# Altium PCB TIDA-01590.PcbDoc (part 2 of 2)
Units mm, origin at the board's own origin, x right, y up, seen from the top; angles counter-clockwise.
Board outline 129.16 x 83.44 mm, 2 copper layers (Top Layer, Bottom Layer), stack 1.646 mm thick; 71 components, 28 nets, 172 pads, 183 vias.
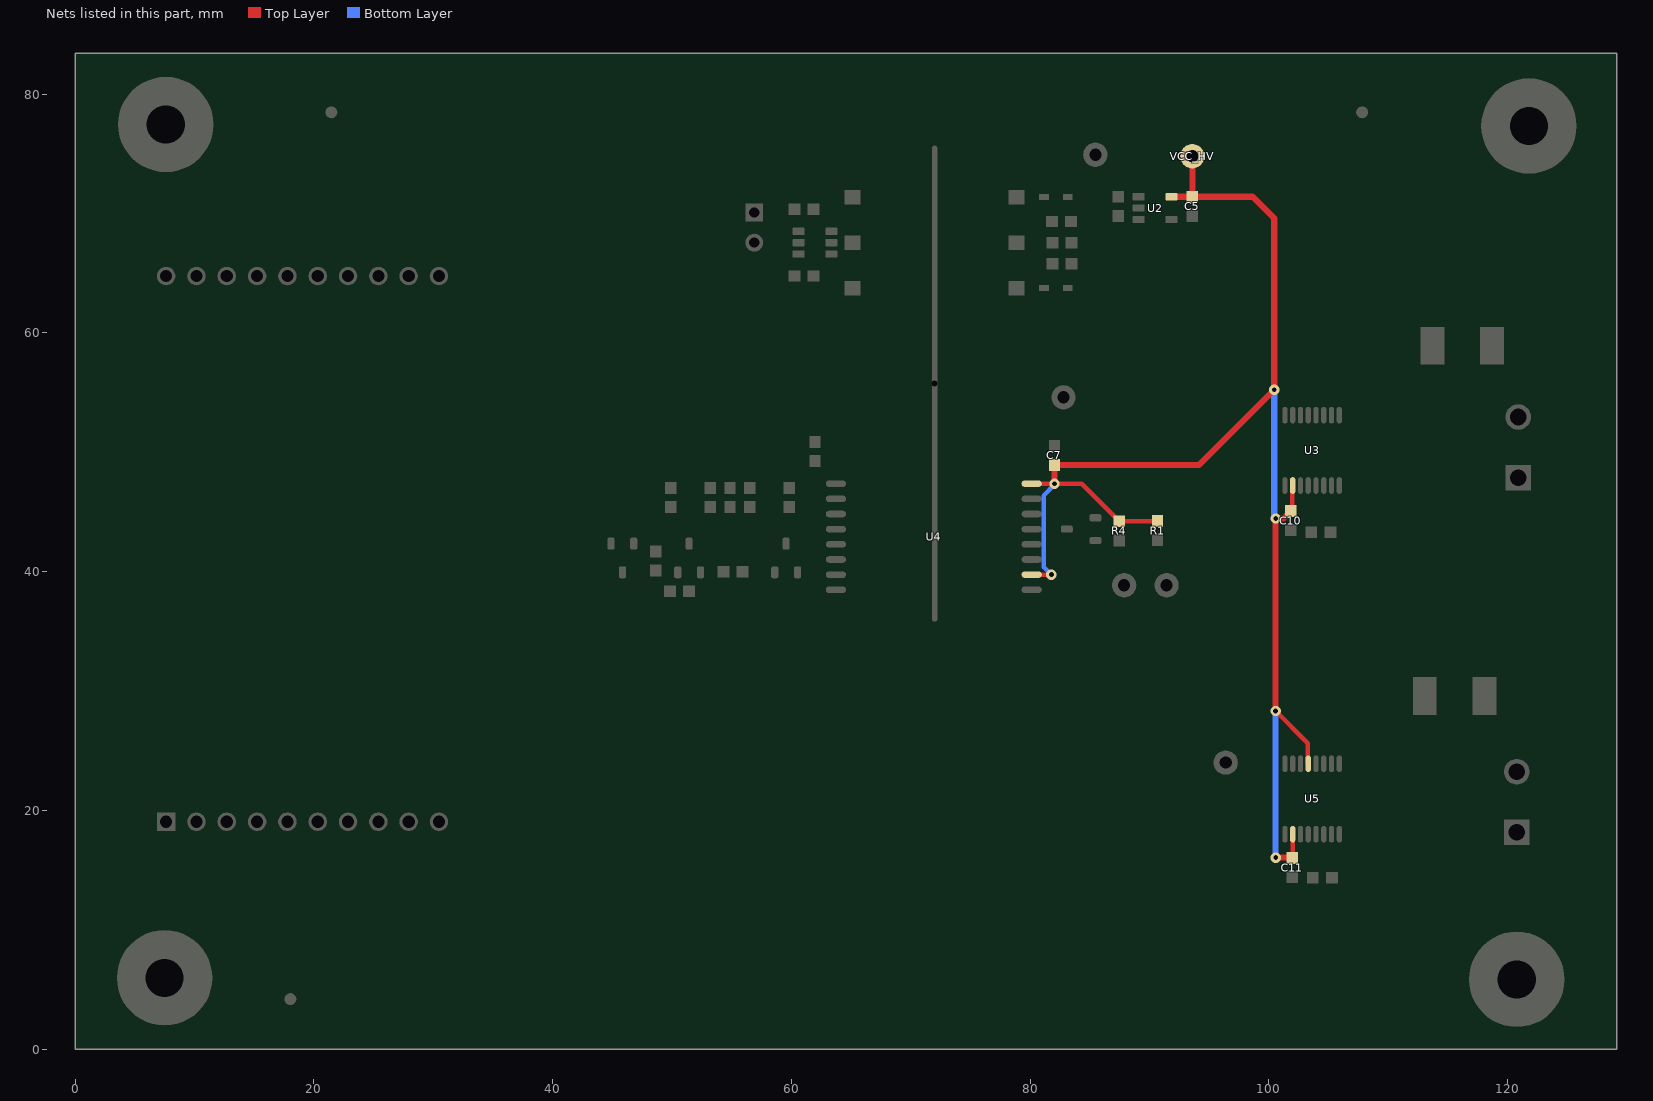
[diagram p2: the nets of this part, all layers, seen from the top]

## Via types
v1: diameter 0.864, hole 0.406, Top Layer to Bottom Layer, tented both sides, 182 vias
v2: diameter 0.965, hole 0.508, Top Layer to Bottom Layer, tented both sides, 1 vias

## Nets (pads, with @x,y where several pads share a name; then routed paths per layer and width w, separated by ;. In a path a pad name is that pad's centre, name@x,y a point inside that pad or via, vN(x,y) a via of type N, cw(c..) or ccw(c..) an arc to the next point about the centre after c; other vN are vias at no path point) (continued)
VCC_HV: C5.1 C7.2 C10.1 C11.1 R1.2 R4.2 U2.5 U3.10 U4.10 U4.16 U5.5 U5.10 VCC_HV.1 | length 123.1
  Top Layer w0.254: 84.328,47.355 84.328,47.371 ; R1.2@90.667,44.223 R1.2@90.678,44.234
  Top Layer w0.381: U4.10@80.209,39.751 v1(81.788,39.751) ; U4.16@80.391,47.371 v1(82.042,47.371) 84.328,47.371 ; 84.328,47.355 R4.2@87.46,44.223 R1.2@90.667,44.223 ; v1(100.575,28.321) 103.276,25.62 103.276,23.936 U5.5@103.307,23.905 ; C10.1@101.854,45.085 101.976,45.207 101.976,47.184 U3.10@102.007,47.215 ; C11.1@101.939,16.044 102.007,16.112 U5.10@102.007,18.005 U5.10@101.981,17.979
  Top Layer w0.508: v1(82.042,47.371) C7.2@82.042,48.946 94.158,48.946 v1(100.457,55.245) 100.457,69.596 98.641,71.412 C5.1@93.599,71.412 ; U2.5@91.853,71.409 93.596,71.409 C5.1@93.599,71.412 ; VCC_HV.1@93.599,74.803 C5.1@93.599,71.412 ; v1(100.575,28.321) 100.575,44.441 v1(100.584,44.45) 101.219,44.45 C10.1@101.854,45.085 ; v1(100.584,16.044) C11.1@101.939,16.044
  Bottom Layer w0.381: v1(81.788,39.751) 81.153,40.386 81.153,46.379 82.042,47.268 v1(82.042,47.371)
  Bottom Layer w0.508: v1(100.457,55.245) 100.457,44.577 v1(100.584,44.45) ; v1(100.575,28.321) 100.575,16.053 v1(100.584,16.044)
pads on no net: D3.2 D4.2 D5.2 FID1.1 FID2.1 FID3.1 H1.1 H2.1 H3.1 H4.1 H8.0 J4.2 J4.3 J4.4 J4.6 J4.7 J4.8 J5.11 J5.12 J5.13 J5.14 J5.15 J5.16 J5.17 J5.18 J5.19 U2.3 U2.4 U3.12 U3.13 U5.12 U5.13

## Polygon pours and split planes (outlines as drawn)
NetJ3_1 on Top Layer "TOP_LAYER_NETJ3_1_P154" (solid, remove dead copper, pour order 154): 104.394,20.667 104.394,16.222 104.394,15.658 104.394,9.525 105.156,8.763 105.881,8.038 120.04,8.038 124.841,14.039 124.841,20.667
NetF1_2 on Top Layer "TOP_LAYER_NETF1_2_P149" (solid, remove dead copper, pour order 149): 104.267,50.165 115.951,50.165 115.951,66.294 105.664,66.294 104.267,64.897
NetF1_1 on Top Layer "TOP_LAYER_NETF1_1_P147" (solid, remove dead copper, pour order 147): 115.951,50.292 124.841,50.292 124.841,65.165 123.917,66.294 115.951,66.294
NetJ2_1 on Top Layer "TOP_LAYER_NETJ2_1_P135" (solid, remove dead copper, pour order 135): 104.394,50.094 104.394,45.649 104.394,45.085 104.394,38.862 105.791,37.465 120.04,37.465 124.841,43.466 124.841,50.094
GND_HV on Top Layer "TOP_LAYER_GND_HV_P140" (solid, remove dead copper, pour order 140): 78.232,73.66 78.232,65.405 79.629,63.881 81.534,61.976 98.425,61.976 99.441,62.865 100.076,63.5 100.076,73.787 98.044,75.819 81.471,75.819
GND on Top Layer "TOP_LAYER_GND_P139" (solid, remove dead copper, pour order 139): 38.735,33.755 38.735,50.165 43.18,54.61 62.23,54.61 63.119,53.721 64.262,52.578 64.262,33.685 60.745,30.988 42.259,30.988
GND_HV on Top Layer "TOP_LAYER_GND_HV_P132" (solid, remove dead copper, pour order 132): 101.981,59.055 82.169,59.055 79.629,56.515 79.629,17.246 88.71,8.001 102.616,8.001 104.14,9.525 104.14,56.896
GND on Top Layer "TOP_LAYER_GND_P138" (solid, remove dead copper, pour order 138): 38.735,74.168 38.735,62.103 43.18,57.658 61.468,57.658 62.865,59.055 64.262,60.452 64.262,73.533 64.008,73.787 61.976,75.819 40.386,75.819
NetF2_1 on Top Layer "TOP_LAYER_NETF2_1_P131" (solid, remove dead copper, pour order 131): 115.951,20.701 124.841,20.701 124.841,35.701 123.917,36.83 115.951,36.83
NetF2_2 on Top Layer "TOP_LAYER_NETF2_2_P148" (solid, remove dead copper, pour order 148): 104.14,20.701 115.951,20.701 115.951,36.83 105.791,36.83 104.14,35.179
NetJ3_1 on Bottom Layer "BOTTOM_LAYER_NETJ3_1_P153" (solid, remove dead copper, pour order 153): 104.394,20.574 104.394,16.222 104.394,15.658 104.394,9.525 105.881,8.038 120.04,8.038 124.841,14.039 124.841,20.574
NetF1_1 on Bottom Layer "BOTTOM_LAYER_NETF1_1_P150" (solid, remove dead copper, pour order 150): 115.951,50.292 124.841,50.292 124.841,65.165 123.917,66.294 115.951,66.294
NetF1_2 on Bottom Layer "BOTTOM_LAYER_NETF1_2_P151" (solid, remove dead copper, pour order 151): 104.267,50.165 115.951,50.165 115.951,66.294 105.664,66.294 104.267,64.897
GND_HV on Bottom Layer "BOTTOM_LAYER_GND_HV_P141" (solid, remove dead copper, pour order 141): 81.47,75.819 96.647,75.819 100.33,72.136 100.33,63.754 99.441,62.865 98.425,61.976 81.534,61.976 80.846,62.664 79.756,63.754 78.232,65.405 78.232,73.66
GND on Bottom Layer "BOTTOM_LAYER_GND_P137" (solid, remove dead copper, pour order 137): 38.735,33.756 38.735,50.165 43.18,54.61 62.23,54.61 64.262,52.578 64.262,33.685 60.745,30.988 42.219,30.988
GND on Bottom Layer "BOTTOM_LAYER_GND_P136" (solid, remove dead copper, pour order 136): 43.18,57.658 61.468,57.658 62.865,59.055 64.262,60.452 64.262,73.533 64.008,73.787 61.976,75.819 40.386,75.819 38.735,74.168 38.735,62.103
NetJ2_1 on Bottom Layer "BOTTOM_LAYER_NETJ2_1_P143" (solid, remove dead copper, pour order 143): 104.394,50.094 104.394,45.649 104.394,45.085 104.394,38.862 105.791,37.465 120.04,37.465 124.841,43.466 124.841,50.094
NetF2_2 on Bottom Layer "BOTTOM_LAYER_NETF2_2_P146" (solid, remove dead copper, pour order 146): 104.14,20.701 115.951,20.701 115.951,36.83 105.791,36.83 104.14,35.179
NetF2_1 on Bottom Layer "BOTTOM_LAYER_NETF2_1_P144" (solid, remove dead copper, pour order 144): 115.951,20.701 124.841,20.701 124.841,35.701 123.917,36.83 115.951,36.83
GND_HV on Bottom Layer "BOTTOM_LAYER_GND_HV_P133" (solid, remove dead copper, pour order 133): 101.981,59.055 82.169,59.055 79.635,56.521 79.635,17.231 88.701,8.001 102.616,8.001 104.146,9.531 104.146,56.89

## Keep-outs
Keep-Out Layer:
  text ".Layer_Name" at 14.656,-24.346 h1.52

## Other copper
Top Layer:
  text ".Layer_Name" at 14.656,-24.346 h1.52
Bottom Layer:
  text ".Layer_Name" at 14.656,-24.346 h1.52

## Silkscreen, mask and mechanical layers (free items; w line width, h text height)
Top Overlay:
  region: 73.66,10.287 66.04,10.287 66.04,7.747 73.66,7.747
  lines w0.381: 126.111,47.879 127.127,47.879 ; 126.238,17.907 127.254,17.907 ; 126.619,41.275 127.254,40.64 ; 126.619,52.451 125.984,53.086 ; 126.619,53.721 125.984,53.086 ; 126.746,11.303 127.381,10.668 ; 126.746,22.479 126.111,23.114 ; 126.746,23.749 126.111,23.114 ; 127.127,65.278 127.127,53.086 125.984,53.086 ; 127.254,35.306 127.254,23.114 126.111,23.114 ; 127.254,47.752 127.254,40.64 ; 127.381,17.78 127.381,10.668 ; 127.889,41.275 127.254,40.64 ; 128.016,11.303 127.381,10.668
  text "GND" at 51.308,69.469 h1.85
  text "3.3 V" at 51.308,66.929 h1.85
  text "HV DC BUS" at 117.602,65.405 h1.85
  text "IN+" at 106.934,52.578 h1.85
  text "IN-" at 106.934,46.482 h1.85
  text "LOAD" at 122.301,39.116 h1.85
  text "HV DC BUS" at 117.602,35.56 h1.85
  text "IN+" at 106.934,23.368 h1.85
  text "IN-" at 106.934,17.272 h1.85
  text "SCL" at 28.575,12.954 h1.85 r90
  text "SDA" at 31.115,12.827 h1.85 r90
  text "ALERT" at 18.415,10.795 h1.85 r90
  text "LOAD" at 121.793,10.16 h1.85
  text ".Layer_Name" at 14.656,-24.346 h1.52
Bottom Overlay:
  text ".Layer_Name" at 14.656,-24.346 h1.52
Top Paste:
  text ".Layer_Name" at 14.656,-24.346 h1.52
Bottom Paste:
  text ".Layer_Name" at 14.656,-24.346 h1.52
Top Solder:
  text ".Layer_Name" at 14.656,-24.346 h1.52
  text ".Layer_Name" at 14.656,-24.346 h1.52
Bottom Solder:
  text ".Layer_Name" at 14.656,-24.346 h1.52
Drill Guide:
  text ".Layer_Name" at 14.656,-24.346 h1.52
M1 Board Outline:
  the board outline again, w0.254
  text ".Layer_Name" at 14.656,-24.346 h1.52
M2 Board Dimensions:
  rectangle: 3.175,-12.7 12.7,-9.525
  rectangle: 0,-9.525 3.175,-6.35
  lines w0.178: 0,-9.525 25.4,-9.525 ; 3.175,-12.7 3.175,-6.35 ; 6.35,-12.7 6.35,-6.35 ; 12.7,-12.7 12.7,-6.35 ; 19.05,-12.7 19.05,-6.35 ; 0,-12.7 0,-6.35 25.4,-6.35 25.4,-12.7 0,-12.7
  text ".Layer_Name" at 14.656,-24.346 h1.52
M3 3D STEP Top:
  text ".Layer_Name" at 14.656,-24.346 h1.52
M4 3D STEP Bottom:
  text ".Layer_Name" at 14.656,-24.346 h1.52
M5 Assembly Top:
  lines w0.254: -7.417,-26.166 160.223,-26.166 ; -7.417,-21.002 160.274,-21.002 ; -7.417,-15.837 -7.417,-31.331 94.31,-31.331 160.274,-31.331 160.274,-15.837 -7.404,-15.837 -7.404,-31.331 32.614,-31.331 ; 55.194,-31.331 55.194,-15.837 ; 87.376,-21.002 87.376,-15.837 ; 108.712,-21.002 108.712,-15.837 ; 124.511,-31.496 124.511,-26.344
  text "COMPONENTS MARKED 'DNP' SHOULD NOT BE POPULATED." at 29.299,-10.63 h1.52
  text "ASSEMBLY VARIANT:" at 29.286,-13.564 h1.52
  text ".VariantName" at 55.601,-13.564 h1.52
  text "PCB VIEWED FROM TOP SIDE" at -5.804,-19.194 h1.52
  text "BOARD #:" at 57.099,-19.194 h1.52
  text ".PRJ_Number" at 70.955,-19.194 h1.52
  text "REV:" at 92.405,-19.194 h1.52
  text ".PCB_Rev" at 99.809,-19.194 h1.52
  text "SVN REV:" at 113.69,-19.194 h1.52
  text ".VersionControl_RevNumber" at 126.543,-19.194 h1.52
  text "TID #:" at 57.099,-24.359 h1.52
  text ".TID" at 70.955,-24.359 h1.52
  text "PLOT NAME =" at -5.804,-29.574 h1.52
  text ".plot_File_Name" at 14.656,-29.574 h1.52
  text "GENERATED    :" at 57.15,-29.574 h1.52
  text ".Print_Date" at 79.235,-29.574 h1.52
  text ".Print_Time" at 97.752,-29.574 h1.52
  text "TEXAS INSTRUMENTS" at 129.87,-29.574 h1.52
M6 Assembly Bottom:
  lines w0.254: -7.429,-21.014 160.261,-21.014 ; -7.379,-26.179 160.261,-26.179 ; 28.334,-31.509 28.334,-26.357 ; 44.133,-21.014 44.133,-15.85 ; 65.468,-21.014 65.468,-15.85 ; 97.65,-31.344 97.65,-15.85 ; 120.231,-31.344 160.249,-31.344 160.249,-15.85 -7.429,-15.85 -7.429,-31.344 58.534,-31.344 160.261,-31.344 160.261,-15.85
  text "COMPONENTS MARKED 'DNP' SHOULD NOT BE POPULATED." at 154.991,-10.617 h1.52
  text ".VariantName" at 128.473,-13.564 h1.52
  text "ASSEMBLY VARIANT:" at 154.864,-13.564 h1.52
  text ".VersionControl_RevNumber" at 26.302,-19.207 h1.52
  text "SVN REV:" at 39.154,-19.207 h1.52
  text ".PCB_Rev" at 53.035,-19.207 h1.52
  text "REV:" at 60.439,-19.207 h1.52
  text ".PRJ_Number" at 81.89,-19.207 h1.52
  text "BOARD #:" at 95.745,-19.207 h1.52
  text "PCB VIEWED FROM BOTTOM SIDE" at 158.648,-19.207 h1.52
  text ".TID" at 81.89,-24.371 h1.52
  text "TID #:" at 95.745,-24.371 h1.52
  text "TEXAS INSTRUMENTS" at 22.974,-29.587 h1.52
  text ".Print_Time" at 55.093,-29.587 h1.52
  text ".Print_Date" at 73.609,-29.587 h1.52
  text "GENERATED    :" at 95.694,-29.587 h1.52
  text ".plot_File_Name" at 138.189,-29.587 h1.52
  text "PLOT NAME =" at 158.648,-29.587 h1.52
M9 Title Sheet:
  drawing of 57 lines, arcs and shapes, not listed
  text "1" at 18.792,201.587 h1.78
  text "2" at 82.182,201.587 h1.78
  text "3" at 145.411,201.587 h1.78
  text "4" at 209.08,201.587 h1.78
  text "5" at 272.555,201.587 h1.78
  text "6" at 336.182,201.587 h1.78
  text "A" at -10.579,172.555 h1.78
  text "A" at 365.341,172.555 h1.78
  text "B" at -10.579,112.103 h1.78
  text "B" at 365.341,112.103 h1.78
  text "C" at -10.579,51.778 h1.78
  text "C" at 365.341,51.778 h1.78
  text "PROJECT TITLE:" at 288.125,4.508 h1.14
  text ".PRJ_Title" at 289.395,1.122 h1.78
  text "DESIGNED FOR:" at 288.125,-3.137 h1.14
  text ".PRJ_Customer" at 289.395,-6.693 h1.78
  text "D" at -10.579,-8.42 h1.78
  text "D" at 365.341,-8.42 h1.78
  text "FILE NAME:" at 288.125,-10.757 h1.14
  text ".PCB_File_Name_No_Path" at 289.395,-13.805 h1.78
  text "Texas Instruments (TI) and/or its licensors do not warrant the accuracy or completeness of this specification" at 161.9,-17.916 h1.14
  text "ENGINEER:" at 288.125,-18.123 h1.14
  text "LAYOUT BY:" at 326.352,-18.123 h1.14
  text "or any information contained therein. TI and/or its licensors do not warrant that this design will meet" at 160.757,-20.777 h1.14
  text ".PRJ_Engineer" at 289.395,-22.06 h1.78
  text ".PCB_Layout" at 327.635,-22.06 h1.78
  text "the specifications, will be suitable for your application or fit for any particular purpose, or will operate in" at 160.757,-23.639 h1.14
  text ".Layer_Name" at 14.656,-24.346 h1.52
  text "ALTIUM DESIGNER VERSION:" at 326.352,-25.997 h1.14
  text "an implementation. TI and/or its licensors do not warrant that the design is production worthy. You should" at 160.757,-26.501 h1.14
  text "completely validate and test your design implementation to confirm the system functionality for your application." at 161.9,-29.362 h1.14
  text ".print_Scale" at 289.395,-29.383 h1.78
  text ".Application_BuildNumber" at 327.635,-29.383 h1.78
  text "1" at 18.792,-34.633 h1.78
  text "2" at 82.182,-34.633 h1.78
  text "3" at 145.411,-34.633 h1.78
  text "4" at 209.08,-34.633 h1.78
  text "5" at 272.555,-34.633 h1.78
  text "6" at 336.182,-34.633 h1.78
M10 Fab Notes:
  drawing of 173 lines, arcs and shapes, not listed
  text "DESIGN INFORMATION" at 314.402,154.965 h1.52
  text "MIN. TRACK WIDTH:" at 298.03,150.393 h1.52
  text "8" at 325.874,150.393 h1.52
  text "MIL" at 329.805,150.393 h1.52
  text "MIN. CLEARANCE:" at 298.03,147.041 h1.52
  text "0.2" at 324.35,147.041 h1.52
  text "mm" at 329.805,147.041 h1.52
  text "MIN. VIA PAD SIZE:" at 298.03,143.688 h1.52
  text "24" at 325.113,143.688 h1.52
  text "MIL" at 329.805,143.688 h1.52
  text "0.05mm (2MIL)" at 315.683,140.088 h1.52
  text "MINIMUM ANNULAR RING" at 289.667,139.98 h1.52
  text "EXTERNAL" at 333.666,139.98 h1.52
  text "PER" at 294.747,136.982 h1.52
  text "IPC-D-275 CLASS 2 LEVEL C" at 300.335,136.982 h1.52
  text "MIL, HOLES" at 338.136,134.13 h1.52
  text "+/-" at 328.168,134.112 h1.52
  text "+/-" at 349.86,134.112 h1.52
  text "REGISTRATION TOLERANCES:" at 289.667,133.985 h1.52
  text "METAL" at 320.142,133.985 h1.52
  text "5" at 334.777,133.985 h1.52
  text "3" at 355.935,133.985 h1.52
  text "MIL" at 358.888,133.985 h1.52
  text "+/-" at 349.86,131.115 h1.52
  text "HOLE SIZE TOLERANCE (UNLESS OTHERWISE SPECIFIED):" at 289.667,130.988 h1.52
  text "3" at 355.935,130.988 h1.52
  text "MIL" at 358.888,130.988 h1.52
  text "MATERIAL:" at 287.768,125.668 h1.52
  text "FR-4 High Tg" at 312.824,122.103 h1.52
  text "FR-408" at 298.462,121.885 h1.52
  text "OTHER" at 336.257,121.885 h1.52
  text "X" at 308.889,121.793 h1.52
  text "62 MIL (1.6mm) +/-10%" at 306.592,117.752 h1.52
  text "THICKNESS:" at 289.667,117.644 h1.52
  text "X" at 303.337,117.644 h1.52
  text "OTHER" at 339.229,117.644 h1.52
  text "TOLERANCE:" at 289.667,113.63 h1.52
  text "X" at 310.986,113.63 h1.52
  text "ANSI IPC-6012 TYPE 3 CLASS 2" at 315.734,113.63 h1.52
  text "OTHER +/-" at 315.734,109.668 h1.52
  text "BOW & TWIST:" at 289.667,105.68 h1.52
  text "X" at 310.986,105.68 h1.52
  text "ANSI IPC-6012 TYPE 3 CLASS 2" at 315.734,105.68 h1.52
  text "OTHER +/-" at 315.734,101.654 h1.52
  text "DRILLING:" at 287.768,98.136 h1.52
  text "REFERENCE:" at 289.667,95.165 h1.52
  text "X" at 306.132,95.165 h1.52
  text "AS SHOWN" at 310.882,95.165 h1.52
  text "X" at 329.018,95.165 h1.52
  text "NC_DRILL FILES" at 332.498,95.165 h1.52
  text "PTH COPPER THICKNESS:" at 289.667,91.151 h1.52
  text "X" at 318.375,91.151 h1.52
  text "20-30 um" at 321.855,91.151 h1.52
  text "OTHER" at 340.067,91.151 h1.52
  text "BOARD FINISH:" at 287.768,87.113 h1.52
  text "SILKSCREEN:" at 291.711,84.116 h1.52
  text "X" at 315.81,84.116 h1.52
  text "TOP" at 319.01,84.116 h1.52
  text "X" at 328.764,84.116 h1.52
  text "BOTTOM" at 331.99,84.116 h1.52
  text "SILKSCREEN COLOR:" at 291.711,79.874 h1.52
  text "X" at 315.783,79.874 h1.52
  text "WHITE" at 319.01,79.874 h1.52
  text "OTHER" at 331.99,79.874 h1.52
  text "X" at 319.111,75.83 h1.52
  text "GREEN" at 322.338,75.83 h1.52
  text "OTHER" at 338.035,75.83 h1.52
  text "SOLDER RESIST COLOR:" at 291.711,75.556 h1.52
  text "X" at 319.111,71.512 h1.52
  text "MATTE" at 322.338,71.512 h1.52
  text "SEMI-GLOSS" at 338.023,71.496 h1.52
  text "IMMERSION GOLD (ENIG)" at 314.718,66.724 h1.52
  text "ENEPIG" at 348.691,66.64 h1.52
  text "SURFACE FINISH:" at 287.768,66.615 h1.52
  text "X" at 309.969,66.615 h1.52
  text "IMM. TIN/SILVER OR EQUIV" at 296.139,62.627 h1.52
  text "OTHER" at 332.498,62.627 h1.52
  text "ARRAY/PANEL:" at 287.768,58.081 h1.52
  text "CUT AND TRIM PER M1 BOARD OUTLINE" at 314.718,57.972 h1.52
  text "N.C. ROUTE" at 314.718,54.118 h1.52
  text "X" at 331.964,54.118 h1.52
  text "V. SCORE" at 336.714,54.118 h1.52
  text "CERTIFICATION:" at 287.768,50.638 h1.52
  text "MATERIALS AND WORKMANSHIP FOR ALL PCBS" at 306.183,50.638 h1.52
  text "TO MEET OR EXCEED THE REQUIREMENTS OF:" at 306.183,48.149 h1.52
  text "X" at 296.696,44.682 h1.52
  text "ANSI IPC-A-600F CLASS ->" at 300.227,44.682 h1.52
  text "X" at 341.859,44.682 h1.52
  text "2" at 344.88,44.682 h1.52
  text "1" at 336.879,44.644 h1.52
  text "3" at 353.872,44.644 h1.52
  text "X" at 317.373,40.631 h1.52
  text "RoHS" at 320.852,40.631 h1.52
  text "OTHER" at 337.22,40.631 h1.52
  text "PER ORDER" at 347.305,40.631 h1.52
  text "ALL BOARDS MUST MEET OR EXCEED UL94-V0 REQUIREMENTS." at 288.468,36.424 h1.52
  text "PCB MUST BEAR THE UL94V-0 UL REGISTERED MATERIAL ID NUMBER" at 288.468,33.376 h1.52
  text "ADDITIONAL REQUIREMENTS:" at 287.768,28.972 h1.52
  text "MICROSECTION:" at 289.667,26.051 h1.52
  text "YES" at 312.673,26.051 h1.52
  text "REQUIRED" at 334.555,22.085 h1.52
  text "BARE BOARD ELEC. TEST:" at 289.667,22.013 h1.52
  text "NONE" at 322.833,22.013 h1.52
  text "X" at 331.329,22.013 h1.52
  text "PER ORDER" at 349.592,22.013 h1.52
  text ".Layer_Name" at 14.656,-24.346 h1.52
M11 Gerber Information:
  lines w0.254: -7.417,-26.166 160.223,-26.166 ; -7.417,-21.002 160.274,-21.002 ; -7.417,-15.837 -7.417,-31.331 94.31,-31.331 160.274,-31.331 160.274,-15.837 -7.404,-15.837 -7.404,-31.331 32.614,-31.331 ; 55.194,-31.331 55.194,-15.837 ; 87.376,-21.002 87.376,-15.837 ; 108.712,-21.002 108.712,-15.837 ; 124.511,-31.496 124.511,-26.344
  text "ALL ARTWORK VIEWED FROM TOP SIDE" at -5.804,-19.194 h1.52
  text "BOARD #:" at 57.099,-19.194 h1.52
  text ".PRJ_Number" at 70.955,-19.194 h1.52
  text "REV:" at 92.405,-19.194 h1.52
  text ".PCB_Rev" at 99.809,-19.194 h1.52
  text "SVN REV:" at 113.69,-19.194 h1.52
  text ".VersionControl_RevNumber" at 126.543,-19.194 h1.52
  text "LAYER NAME =" at -5.804,-24.346 h1.52
  text "TID #:" at 57.099,-24.359 h1.52
  text ".TID" at 70.955,-24.359 h1.52
  text "PLOT NAME =" at -5.804,-29.574 h1.52
  text ".plot_File_Name" at 14.656,-29.574 h1.52
  text "GENERATED    :" at 57.15,-29.574 h1.52
  text ".Print_Date" at 79.235,-29.574 h1.52
  text ".Print_Time" at 97.752,-29.574 h1.52
  text "TEXAS INSTRUMENTS" at 129.87,-29.574 h1.52
M12 Stackup:
  drawing of 191 lines, arcs and shapes, not listed
  text "Layer" at 248.865,196.342 h1.52
  text "Name" at 259.277,196.342 h1.52
  text "Material" at 282.892,196.342 h1.52
  text "Thickness" at 304.731,196.342 h1.52
  text "Constant" at 321.236,196.342 h1.52
  text "Board Layer Stack" at 335.711,196.342 h1.52
  text "1" at 248.865,193.294 h1.52
  text "Top Overlay" at 259.277,193.294 h1.52
  text "2" at 248.865,190.246 h1.52
  text "Top Solder" at 259.277,190.246 h1.52
  text "Solder Resist" at 282.892,190.246 h1.52
  text "0.40mil" at 304.731,190.246 h1.52
  text "3.5" at 321.236,190.246 h1.52
  text "3" at 248.865,187.198 h1.52
  text "Top Layer" at 259.277,187.198 h1.52
  text "Copper" at 282.892,187.198 h1.52
  text "2.80mil" at 304.731,187.198 h1.52
  text "4" at 248.865,184.15 h1.52
  text "Dielectric1" at 259.277,184.15 h1.52
  text "FR-4" at 282.892,184.15 h1.52
  text "59.20mil" at 304.731,184.15 h1.52
  text "4.8" at 321.236,184.15 h1.52
  text "5" at 248.865,181.102 h1.52
  text "Bottom Layer" at 259.277,181.102 h1.52
  text "Copper" at 282.892,181.102 h1.52
  text "2.80mil" at 304.731,181.102 h1.52
  text "6" at 248.865,178.054 h1.52
  text "Bottom Solder" at 259.277,178.054 h1.52
  text "Solder Resist" at 282.892,178.054 h1.52
  text "0.40mil" at 304.731,178.054 h1.52
  text "3.5" at 321.236,178.054 h1.52
  text "7" at 248.865,175.006 h1.52
  text "Bottom Overlay" at 259.277,175.006 h1.52
  text ".Layer_Name" at 14.656,-24.346 h1.52
M13 Component Bodies Top:
  text ".Layer_Name" at 14.656,-24.346 h1.52
M14 Component Bodies Bottom:
  text ".Layer_Name" at 14.656,-24.346 h1.52
M15 Courtyards Top:
  text ".Layer_Name" at 14.656,-24.346 h1.52
M16 Courtyards Bottom:
  text ".Layer_Name" at 14.656,-24.346 h1.52
Drill Drawing:
  circle w0.254: c160.398,66.236 r0.562
  lines w0.254: 159.836,63.424 160.117,63.424 160.398,63.143 160.679,63.424 160.96,63.424 160.679,63.705 160.96,63.987 160.679,63.987 160.398,64.268 160.117,63.987 159.836,63.987 160.117,63.705 159.836,63.424 ; 159.836,68.485 160.117,68.485 160.117,68.204 160.679,68.204 160.679,68.485 160.96,68.485 160.96,69.047 160.679,69.047 160.679,69.329 160.117,69.329 160.117,69.047 159.836,69.047 159.836,68.485 ; 159.836,70.734 159.836,71.016 160.117,71.297 159.836,71.578 159.836,71.859 160.117,71.859 160.398,71.578 160.679,71.859 160.96,71.859 160.96,71.578 160.679,71.297 160.96,71.016 160.96,70.734 160.679,70.734 160.398,71.016 160.117,70.734 159.836,70.734 ; 159.836,73.265 160.398,73.546 160.96,73.265 160.679,73.827 160.96,74.389 160.398,74.108 159.836,74.389 160.117,73.827 159.836,73.265 ; 159.836,76.92 160.96,76.92 160.398,75.795 159.836,76.92 ; 159.836,78.326 160.96,78.326 160.96,79.45 159.836,79.45 159.836,78.326 ; 159.836,81.418 160.398,80.856 160.96,81.418 160.398,81.981 159.836,81.418
  lines w0.305: 158.8,62.384 237.869,62.384 ; 158.8,82.627 237.869,82.627 ; 166.817,59.854 166.817,85.158 ; 174.874,59.854 174.874,85.158 ; 190.666,59.854 190.666,85.158 ; 196.872,59.854 196.872,85.158 ; 206.025,59.854 206.025,85.158 ; 224.046,59.854 224.046,85.158 ; 158.8,59.854 237.869,59.854 237.869,85.158 158.8,85.158 158.8,59.854
  text "Symbol" at 160.319,83.386 h1.83
  text "Quantity" at 167.577,83.386 h1.83
  text "Finished Hole Size" at 175.633,83.386 h1.83
  text "Plated" at 191.425,83.386 h1.83
  text "Hole Type" at 197.631,83.386 h1.83
  text "Drill Layer Pair" at 206.784,83.386 h1.83
  text "Hole Tolerance" at 224.805,83.386 h1.83
  text "182" at 167.577,80.856 h1.52
  text "16.00mil (0.406mm)" at 175.633,80.856 h1.52
  text "PTH" at 191.425,80.856 h1.52
  text "Round" at 197.631,80.856 h1.52
  text "Top Layer - Bottom Layer" at 206.784,80.856 h1.52
  text "1" at 167.577,78.326 h1.52
  text "20.00mil (0.508mm)" at 175.633,78.326 h1.52
  text "PTH" at 191.425,78.326 h1.52
  text "Round" at 197.631,78.326 h1.52
  text "Top Layer - Bottom Layer" at 206.784,78.326 h1.52
  text "2" at 167.577,75.795 h1.52
  text "33.46mil (0.850mm)" at 175.633,75.795 h1.52
  text "PTH" at 191.425,75.795 h1.52
  text "Round" at 197.631,75.795 h1.52
  text "Top Layer - Bottom Layer" at 206.784,75.795 h1.52
  text "6" at 167.577,73.265 h1.52
  text "40.00mil (1.016mm)" at 175.633,73.265 h1.52
  text "PTH" at 191.425,73.265 h1.52
  text "Round" at 197.631,73.265 h1.52
  text "Top Layer - Bottom Layer" at 206.784,73.265 h1.52
  text "20" at 167.577,70.734 h1.52
  text "40.16mil (1.020mm)" at 175.633,70.734 h1.52
  text "PTH" at 191.425,70.734 h1.52
  text "Round" at 197.631,70.734 h1.52
  text "Top Layer - Bottom Layer" at 206.784,70.734 h1.52
  text "4" at 167.577,68.204 h1.52
  text "55.12mil (1.400mm)" at 175.633,68.204 h1.52
  text "PTH" at 191.425,68.204 h1.52
  text "Round" at 197.631,68.204 h1.52
  text "Top Layer - Bottom Layer" at 206.784,68.204 h1.52
  text "4" at 167.577,65.674 h1.52
  text "125.98mil (3.200mm)" at 175.633,65.674 h1.52
  text "PTH" at 191.425,65.674 h1.52
  text "Round" at 197.631,65.674 h1.52
  text "Top Layer - Bottom Layer" at 206.784,65.674 h1.52
  text "1" at 167.577,63.143 h1.52
  text "20.00mil (0.508mm)" at 175.633,63.143 h1.52
  text "NPTH" at 191.425,63.143 h1.52
  text "Slot" at 197.631,63.143 h1.52
  text "Top Layer - Bottom Layer" at 206.784,63.143 h1.52
  text "220 Total" at 167.577,60.613 h1.52
  text "Slot definitions :" at 160.319,58.591 h1.52
  text "Routed Path Length" at 171.579,58.591 h1.52
  text "= Calculated from tool start centre position to tool end centre position." at 185.1,58.591 h1.52
  text "Hole Length" at 171.579,57.327 h1.52
  text "= Routed Path Length + Tool Size = Slot length as defined in the PCB layout" at 180.025,57.327 h1.52
  text ".Layer_Name" at 14.656,-24.346 h1.52
M17 Embedded Cavity:
  text ".Layer_Name" at 14.656,-24.346 h1.52
M18 Embedded Assembly:
  text ".Layer_Name" at 14.656,-24.346 h1.52
M19 Embedded Keepout:
  text ".Layer_Name" at 14.656,-24.346 h1.52

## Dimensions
0,0 to 129.159,0 on M2 Board Dimensions
0,0 to 0,83.439 on M2 Board Dimensions
0,-12.7 to 25.4,-12.7 on M2 Board Dimensions
7.62,64.77 to 7.62,19.05 on M2 Board Dimensions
